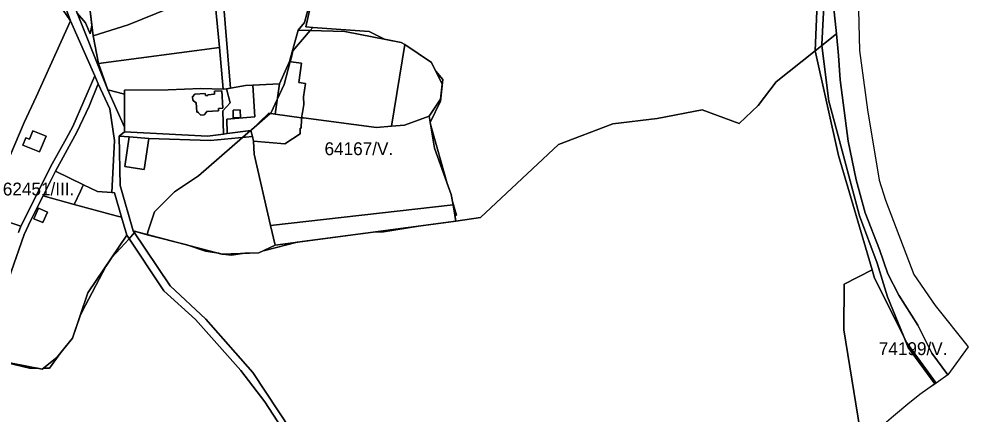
# Model space of a CAD drawing. Extents: x -502026 to -497664, y -1143484 to -1138019.
# Drawn here: x -498590 to -497998, y -1141865 to -1141619 of the extents above; entities that cross this region are included whole.
import ezdxf

# ---------------------------------------------------------------- set-up
doc = ezdxf.new("R2010")
doc.units = 0
for name, color, linetype in [('25', 7, 'Continuous'), ('31', 7, 'Continuous'), ('37', 7, 'Continuous'), ('43', 7, 'Continuous'), ('49', 7, 'Continuous'), ('55', 7, 'Continuous'), ('62', 7, 'Continuous')]:
    doc.layers.add(name, color=color, linetype=linetype)

msp = doc.modelspace()

# ---------------------------------------------------------------- linework, layer by layer
at = {"layer": '25'}
for points in [[(-498462.48, -1141662.97), (-498476.51, -1141662.61), (-498496.86, -1141663.41), (-498524.14, -1141663.5), (-498524.13, -1141666.14), (-498534.51, -1141663.26), (-498540.35, -1141646.84), (-498464.9, -1141637.05)], [(-498334.06, -1141679.76), (-498349.48, -1141685.31), (-498357.49, -1141685.92), (-498349.26, -1141635.03), (-498332.54, -1141646.31), (-498325.9, -1141659.82), (-498327, -1141669.23)], [(-498430.11, -1141678.47), (-498434.11, -1141677.92), (-498445.33, -1141688.68), (-498460.08, -1141690.61), (-498460.31, -1141681.6), (-498442.77, -1141680.09), (-498444.03, -1141660.43), (-498427.35, -1141659.64)], [(-498462.48, -1141662.97), (-498460.46, -1141662.63), (-498458.17, -1141671.36), (-498462.83, -1141676.38), (-498462.4, -1141690.91), (-498472.24, -1141692.2), (-498524.02, -1141689.63), (-498524.04, -1141686.55), (-498524.13, -1141666.14), (-498524.14, -1141663.5), (-498496.86, -1141663.41), (-498476.51, -1141662.61)], [(-498463.44, -1141663.99), (-498467.96, -1141664.27), (-498467.87, -1141666.06), (-498472.1, -1141666.37), (-498472.07, -1141666.85), (-498473.67, -1141666.95), (-498473.74, -1141665.69), (-498480.29, -1141666.13), (-498481.67, -1141667.66), (-498481.52, -1141669.75), (-498479.86, -1141671.22), (-498479.4, -1141671.18), (-498478.93, -1141677.34), (-498478.06, -1141677.28), (-498478.02, -1141677.75), (-498476.5, -1141679.05), (-498474.37, -1141678.93), (-498472.94, -1141677.35), (-498472.96, -1141676.88), (-498465.5, -1141676.39), (-498465.55, -1141674.89), (-498462.76, -1141674.71)], [(-498532.03, -1141727.36), (-498530.29, -1141727.52), (-498525.92, -1141742.8), (-498529.35, -1141741.87), (-498555.48, -1141734.78), (-498551.6, -1141726.45), (-498549.9, -1141722.79), (-498549.76, -1141722.49), (-498540.93, -1141726.8)]]:
    msp.add_lwpolyline(points, close=True, dxfattribs=at)
at = {"layer": '31'}
for points in [[(-498349.26, -1141635.03), (-498357.49, -1141685.92), (-498366.94, -1141686.74), (-498412.32, -1141680.91), (-498413.62, -1141680.73), (-498413.05, -1141677.56), (-498412.15, -1141672.54), (-498412.38, -1141667.61), (-498411.22, -1141659.31), (-498415.3, -1141658.74), (-498413.61, -1141646.71), (-498418.58, -1141646.01), (-498421.21, -1141645.64), (-498415.78, -1141626.22), (-498386.55, -1141627.03), (-498351.49, -1141633.83)], [(-498319.11, -1141735.05), (-498432.94, -1141748.03), (-498443.3, -1141703.42), (-498443.65, -1141695.34), (-498424.08, -1141697), (-498414.58, -1141690.77), (-498414.59, -1141687.27), (-498413.79, -1141687.29), (-498413.64, -1141681.68), (-498413.62, -1141680.73), (-498412.32, -1141680.91), (-498366.94, -1141686.74), (-498357.49, -1141685.92), (-498349.48, -1141685.31), (-498334.06, -1141679.76), (-498330.58, -1141699.76), (-498320.36, -1141728.58)], [(-498521.14, -1141692.7), (-498523.9, -1141711.15), (-498515.99, -1141712.34), (-498511.76, -1141712.97), (-498508.92, -1141693.77), (-498470.48, -1141694.85), (-498444.29, -1141692.51), (-498443.65, -1141695.34), (-498443.3, -1141703.42), (-498432.94, -1141748.03), (-498430.11, -1141760.24), (-498440.19, -1141765.02), (-498463.46, -1141765.75), (-498518.8, -1141751.37), (-498526.77, -1141723.05), (-498527.53, -1141692.29)], [(-498555.48, -1141734.78), (-498529.35, -1141741.87), (-498525.92, -1141742.8), (-498522.72, -1141754.01), (-498546.95, -1141790.01), (-498556.66, -1141818.24), (-498566.28, -1141830.25), (-498575.47, -1141837.59), (-498613.88, -1141829.95), (-498603.5, -1141800.08), (-498596.59, -1141781.61), (-498586.82, -1141753.62), (-498582.48, -1141744.58), (-498574.93, -1141729.51)], [(-498572.26, -1141739.56), (-498577.86, -1141737.22), (-498580.61, -1141743.72), (-498575.01, -1141746.06)]]:
    msp.add_lwpolyline(points, close=True, dxfattribs=at)
at = {"layer": '37'}
for points in [[(-498468.3, -1141600.99), (-498521.83, -1141622.73), (-498543.68, -1141629.6), (-498545.55, -1141614.01), (-498540.19, -1141601.73), (-498472.52, -1141589.85)], [(-498557.86, -1141620.31), (-498579.16, -1141667.75), (-498586.65, -1141683.62), (-498595.46, -1141704.28), (-498611.77, -1141740.81), (-498648.14, -1141728.24), (-498683.59, -1141712.28), (-498669.98, -1141686.66), (-498667.93, -1141675.26), (-498657.61, -1141653.21), (-498650.99, -1141654.52), (-498639.74, -1141648.11), (-498633.36, -1141630.35), (-498644.79, -1141624.98), (-498644.02, -1141617.12), (-498624.09, -1141623.37), (-498616.79, -1141615.76), (-498612.61, -1141616.54), (-498606.51, -1141611.58), (-498603.56, -1141602.08), (-498594.48, -1141602.56), (-498583.73, -1141606.31), (-498572.2, -1141605.96), (-498562.32, -1141613.57)], [(-498468.16, -1141602.47), (-498464.9, -1141637.05), (-498540.35, -1141646.84), (-498543.68, -1141629.6), (-498521.83, -1141622.73), (-498468.3, -1141600.99)], [(-498415.78, -1141626.22), (-498421.21, -1141645.64), (-498427.35, -1141659.64), (-498444.03, -1141660.43), (-498448.55, -1141660.65), (-498458.03, -1141662.23), (-498463.01, -1141601.55), (-498407.52, -1141604.91), (-498411.73, -1141621.35)], [(-498542.66, -1141654.6), (-498556.29, -1141686.3), (-498560.31, -1141693.56), (-498569.25, -1141709.41), (-498588.89, -1141748.42), (-498611.77, -1141740.81), (-498595.46, -1141704.28), (-498586.65, -1141683.62), (-498579.16, -1141667.75), (-498557.86, -1141620.31)], [(-498573.03, -1141692.28), (-498581.23, -1141688.88), (-498583.43, -1141694.19), (-498585.72, -1141693.25), (-498587.59, -1141697.76), (-498577.07, -1141702.1)], [(-498317.26, -1141745.25), (-498430.11, -1141760.24), (-498432.94, -1141748.03), (-498319.11, -1141735.05)], [(-498017.71, -1141846.21), (-498022.83, -1141849.82), (-498027.83, -1141853.34), (-498029.01, -1141854.28), (-498034.07, -1141858.33), (-498044.28, -1141866.85), (-498050.16, -1141871.76), (-498065.32, -1141874.58), (-498075.32, -1141812.96), (-498074.98, -1141784.5), (-498057.54, -1141775.53), (-498056.02, -1141780.8), (-498035.83, -1141821.06)]]:
    msp.add_lwpolyline(points, close=True, dxfattribs=at)
at = {"layer": '43'}
for points in [[(-498090.08, -1141564.22), (-498093.13, -1141638.94), (-498117.43, -1141658.42), (-498128.73, -1141673.11), (-498140.46, -1141684.3), (-498163.59, -1141675.75), (-498191.81, -1141681.3), (-498219.34, -1141684.54), (-498253.35, -1141697.5), (-498301.98, -1141743.03), (-498317.26, -1141745.25), (-498319.11, -1141735.05), (-498320.36, -1141728.58), (-498330.58, -1141699.76), (-498334.06, -1141679.76), (-498327, -1141669.23), (-498325.9, -1141659.82), (-498332.54, -1141646.31), (-498349.26, -1141635.03), (-498351.49, -1141633.83), (-498386.55, -1141627.03), (-498415.78, -1141626.22), (-498411.73, -1141621.35), (-498407.52, -1141604.91)], [(-498562.69, -1141607.49), (-498557.86, -1141620.31), (-498562.32, -1141613.57)], [(-498545.55, -1141614.01), (-498543.68, -1141629.6), (-498540.35, -1141646.84), (-498534.51, -1141663.26), (-498556.46, -1141608.73)], [(-498420.03, -1141875.81), (-498444.04, -1141839.62), (-498473.4, -1141806.35), (-498495.69, -1141785.66), (-498518.8, -1141751.37), (-498463.46, -1141765.75), (-498440.19, -1141765.02), (-498430.11, -1141760.24), (-498317.26, -1141745.25), (-498301.98, -1141743.03), (-498253.35, -1141697.5), (-498219.34, -1141684.54), (-498191.81, -1141681.3), (-498163.59, -1141675.75), (-498140.46, -1141684.3), (-498128.73, -1141673.11), (-498117.43, -1141658.42), (-498093.13, -1141638.94), (-498078.53, -1141704.32), (-498057.54, -1141775.53), (-498074.98, -1141784.5), (-498075.32, -1141812.96), (-498065.32, -1141874.58)], [(-498611.77, -1141740.81), (-498588.89, -1141748.42), (-498590.32, -1141752.32)], [(-498613.88, -1141829.95), (-498575.47, -1141837.59), (-498566.28, -1141830.25), (-498556.66, -1141818.24), (-498546.95, -1141790.01), (-498522.72, -1141754.01), (-498499.6, -1141788.79), (-498479.77, -1141806.48), (-498451.59, -1141838.3), (-498436.54, -1141857.84), (-498423.37, -1141878.17)]]:
    msp.add_lwpolyline(points, dxfattribs=at)
at = {"layer": '49'}
msp.add_lwpolyline([(-498066.45, -1141596.33), (-498065.44, -1141638.73), (-498060.4, -1141675.82), (-498053.14, -1141719.76), (-498049.24, -1141732.06), (-498031.51, -1141778.56), (-498018.34, -1141797.77), (-497997.74, -1141823.63), (-498010.44, -1141841.03), (-498020.42, -1141827.63), (-498029.15, -1141810.09), (-498041.01, -1141791.41), (-498047.77, -1141778.15), (-498052.88, -1141762.94), (-498061.89, -1141740.12), (-498067.62, -1141719.38), (-498072.53, -1141695.32), (-498077.57, -1141657.19), (-498078.46, -1141642.04), (-498079.89, -1141628.43), (-498081.67, -1141610.69)], dxfattribs=at)
at = {"layer": '55'}
for points in [[(-498081.67, -1141610.69), (-498079.89, -1141628.43), (-498093.13, -1141638.94), (-498090.08, -1141564.22)], [(-498423.37, -1141878.17), (-498436.54, -1141857.84), (-498451.59, -1141838.3), (-498479.77, -1141806.48), (-498499.6, -1141788.79), (-498522.72, -1141754.01), (-498525.92, -1141742.8), (-498530.29, -1141727.52), (-498532.03, -1141727.36), (-498530.34, -1141694.84), (-498533.18, -1141675.22), (-498540.46, -1141659.57), (-498542.66, -1141654.6), (-498557.86, -1141620.31), (-498562.69, -1141607.49)], [(-498556.46, -1141608.73), (-498534.51, -1141663.26), (-498524.04, -1141686.55), (-498524.02, -1141689.63), (-498527.53, -1141692.29), (-498526.77, -1141723.05), (-498518.8, -1141751.37), (-498495.69, -1141785.66), (-498473.4, -1141806.35), (-498444.04, -1141839.62), (-498420.03, -1141875.81)], [(-498590.32, -1141752.32), (-498588.89, -1141748.42), (-498569.25, -1141709.41), (-498560.31, -1141693.56), (-498556.29, -1141686.3), (-498542.66, -1141654.6), (-498540.46, -1141659.57), (-498546.22, -1141673.43), (-498553.93, -1141689.66), (-498567.2, -1141714.11), (-498574.93, -1141729.51), (-498582.48, -1141744.58), (-498586.82, -1141753.62), (-498596.59, -1141781.61)]]:
    msp.add_lwpolyline(points, dxfattribs=at)
for points in [[(-498458.03, -1141662.23), (-498460.46, -1141662.63), (-498462.48, -1141662.97), (-498464.9, -1141637.05), (-498468.16, -1141602.47), (-498463.01, -1141601.55)], [(-498010.44, -1141841.03), (-498017.71, -1141846.21), (-498035.83, -1141821.06), (-498056.02, -1141780.8), (-498057.54, -1141775.53), (-498078.53, -1141704.32), (-498093.13, -1141638.94), (-498079.89, -1141628.43), (-498078.46, -1141642.04), (-498077.57, -1141657.19), (-498072.53, -1141695.32), (-498067.62, -1141719.38), (-498061.89, -1141740.12), (-498052.88, -1141762.94), (-498047.77, -1141778.15), (-498041.01, -1141791.41), (-498029.15, -1141810.09), (-498020.42, -1141827.63)], [(-498413.62, -1141680.73), (-498430.11, -1141678.47), (-498427.35, -1141659.64), (-498421.21, -1141645.64), (-498418.58, -1141646.01), (-498413.61, -1141646.71), (-498415.3, -1141658.74), (-498411.22, -1141659.31), (-498412.38, -1141667.61), (-498412.15, -1141672.54), (-498413.05, -1141677.56)], [(-498532.03, -1141727.36), (-498540.93, -1141726.8), (-498549.76, -1141722.49), (-498567.2, -1141714.11), (-498553.93, -1141689.66), (-498546.22, -1141673.43), (-498540.46, -1141659.57), (-498533.18, -1141675.22), (-498530.34, -1141694.84)], [(-498460.08, -1141690.61), (-498462.4, -1141690.91), (-498462.83, -1141676.38), (-498458.17, -1141671.36), (-498460.46, -1141662.63), (-498458.03, -1141662.23), (-498448.55, -1141660.65), (-498444.03, -1141660.43), (-498442.77, -1141680.09), (-498460.31, -1141681.6)], [(-498524.13, -1141666.14), (-498524.04, -1141686.55), (-498534.51, -1141663.26)], [(-498463.44, -1141663.99), (-498462.76, -1141674.71), (-498465.55, -1141674.89), (-498465.5, -1141676.39), (-498472.96, -1141676.88), (-498472.94, -1141677.35), (-498474.37, -1141678.93), (-498476.5, -1141679.05), (-498478.02, -1141677.75), (-498478.06, -1141677.28), (-498478.93, -1141677.34), (-498479.4, -1141671.18), (-498479.86, -1141671.22), (-498481.52, -1141669.75), (-498481.67, -1141667.66), (-498480.29, -1141666.13), (-498473.74, -1141665.69), (-498473.67, -1141666.95), (-498472.07, -1141666.85), (-498472.1, -1141666.37), (-498467.87, -1141666.06), (-498467.96, -1141664.27)], [(-498451.76, -1141680.75), (-498456.22, -1141680.87), (-498456.39, -1141676.06), (-498451.86, -1141675.88)], [(-498451.76, -1141680.75), (-498451.86, -1141675.88), (-498456.39, -1141676.06), (-498456.22, -1141680.87)], [(-498430.11, -1141678.47), (-498413.62, -1141680.73), (-498413.64, -1141681.68), (-498413.79, -1141687.29), (-498414.59, -1141687.27), (-498414.58, -1141690.77), (-498424.08, -1141697), (-498443.65, -1141695.34), (-498444.29, -1141692.51), (-498445.33, -1141688.68), (-498434.11, -1141677.92)], [(-498573.03, -1141692.28), (-498577.07, -1141702.1), (-498587.59, -1141697.76), (-498585.72, -1141693.25), (-498583.43, -1141694.19), (-498581.23, -1141688.88)], [(-498444.29, -1141692.51), (-498470.48, -1141694.85), (-498508.92, -1141693.77), (-498521.14, -1141692.7), (-498527.53, -1141692.29), (-498524.02, -1141689.63), (-498472.24, -1141692.2), (-498462.4, -1141690.91), (-498460.08, -1141690.61), (-498445.33, -1141688.68)], [(-498508.92, -1141693.77), (-498511.76, -1141712.97), (-498515.99, -1141712.34), (-498523.9, -1141711.15), (-498521.14, -1141692.7)], [(-498549.76, -1141722.49), (-498549.9, -1141722.79), (-498551.6, -1141726.45), (-498555.48, -1141734.78), (-498574.93, -1141729.51), (-498567.2, -1141714.11)], [(-498572.26, -1141739.56), (-498575.01, -1141746.06), (-498580.61, -1141743.72), (-498577.86, -1141737.22)]]:
    msp.add_lwpolyline(points, close=True, dxfattribs=at)
at = {"layer": '62'}
for points in [[(-498066.45, -1141596.33), (-498065.44, -1141638.73), (-498060.4, -1141675.82), (-498053.14, -1141719.76), (-498049.24, -1141732.06), (-498031.51, -1141778.56), (-498018.34, -1141797.77), (-497997.74, -1141823.63), (-498010.44, -1141841.03), (-498017.71, -1141846.21), (-498018.52, -1141846.78), (-498035, -1141824), (-498037.99, -1141816.74), (-498038.02, -1141816.67), (-498048, -1141792.5), (-498054.5, -1141771.5), (-498065.5, -1141742), (-498079.5, -1141689), (-498084.5, -1141670.5), (-498088.92, -1141635.6), (-498089, -1141635), (-498087, -1141599)], [(-498087, -1141599), (-498089, -1141635), (-498088.92, -1141635.6), (-498084.5, -1141670.5), (-498079.5, -1141689), (-498065.5, -1141742), (-498054.5, -1141771.5), (-498048, -1141792.5), (-498038.02, -1141816.67), (-498056.02, -1141780.8), (-498057.54, -1141775.53), (-498074.98, -1141784.5), (-498075.32, -1141812.96), (-498065.32, -1141874.58)], [(-498406.5, -1141604.5), (-498411, -1141624), (-498406.5, -1141624.5), (-498408.16, -1141626.43), (-498419, -1141639), (-498420, -1141643), (-498420.72, -1141645.71), (-498424.5, -1141660), (-498428.77, -1141669.35), (-498432.5, -1141677.5), (-498433.14, -1141678.05), (-498444.87, -1141688.24), (-498445.33, -1141688.68), (-498445.39, -1141688.69), (-498450.42, -1141693.06), (-498478, -1141717), (-498493, -1141727), (-498505.5, -1141739.5), (-498509.5, -1141752), (-498509.95, -1141753.67), (-498517.25, -1141751.77), (-498517.99, -1141752.57), (-498521.29, -1141756.16), (-498532.06, -1141767.89), (-498535.82, -1141773.47), (-498550.5, -1141801.5), (-498551.86, -1141804.27), (-498556.66, -1141818.24), (-498563.85, -1141827.22), (-498571, -1141837), (-498574.73, -1141837), (-498575.47, -1141837.59), (-498578.44, -1141837), (-498583.5, -1141837), (-498608.01, -1141831.12)], [(-498608.01, -1141831.12), (-498583.5, -1141837), (-498578.44, -1141837), (-498575.47, -1141837.59), (-498574.73, -1141837), (-498571, -1141837), (-498563.85, -1141827.22), (-498556.66, -1141818.24), (-498551.86, -1141804.27), (-498550.5, -1141801.5), (-498535.82, -1141773.47), (-498532.06, -1141767.89), (-498521.29, -1141756.16), (-498517.99, -1141752.57), (-498517.25, -1141751.77), (-498509.95, -1141753.67), (-498485.19, -1141760.1), (-498473.5, -1141764), (-498465.21, -1141765.29), (-498463.46, -1141765.75), (-498462.49, -1141765.72), (-498457.5, -1141766.5), (-498449.1, -1141765.3), (-498440.19, -1141765.02), (-498437.19, -1141763.6), (-498436.5, -1141763.5), (-498416.41, -1141758.42), (-498368.86, -1141752.1), (-498362.5, -1141752), (-498340.61, -1141748.35), (-498317.26, -1141745.25), (-498317.89, -1141741.79), (-498317, -1141741.5), (-498319.52, -1141732.94), (-498320.36, -1141728.58), (-498322.78, -1141721.77), (-498333.04, -1141685.62), (-498333.37, -1141683.73), (-498327, -1141670.5), (-498325.5, -1141657), (-498329.85, -1141651.77), (-498332.54, -1141646.31), (-498349.26, -1141635.03), (-498351.49, -1141633.83), (-498361.86, -1141631.82), (-498371.5, -1141627), (-498406.5, -1141624.5), (-498411, -1141624), (-498406.5, -1141604.5)], [(-498553.69, -1141615.62), (-498548.5, -1141621.5), (-498545.5, -1141628.5), (-498544.44, -1141623.22), (-498545.55, -1141614.01)], [(-498545.55, -1141614.01), (-498544.44, -1141623.22), (-498545.5, -1141628.5), (-498548.5, -1141621.5), (-498553.69, -1141615.62)]]:
    msp.add_lwpolyline(points, dxfattribs=at)
for points in [[(-498509.95, -1141753.67), (-498509.5, -1141752), (-498505.5, -1141739.5), (-498493, -1141727), (-498478, -1141717), (-498450.42, -1141693.06), (-498445.39, -1141688.69), (-498445.33, -1141688.68), (-498444.87, -1141688.24), (-498433.14, -1141678.05), (-498432.5, -1141677.5), (-498428.77, -1141669.35), (-498424.5, -1141660), (-498420.72, -1141645.71), (-498420, -1141643), (-498419, -1141639), (-498408.16, -1141626.43), (-498406.5, -1141624.5), (-498371.5, -1141627), (-498361.86, -1141631.82), (-498351.49, -1141633.83), (-498349.26, -1141635.03), (-498332.54, -1141646.31), (-498329.85, -1141651.77), (-498325.5, -1141657), (-498327, -1141670.5), (-498333.37, -1141683.73), (-498333.04, -1141685.62), (-498322.78, -1141721.77), (-498320.36, -1141728.58), (-498319.52, -1141732.94), (-498317, -1141741.5), (-498317.89, -1141741.79), (-498317.26, -1141745.25), (-498340.61, -1141748.35), (-498362.5, -1141752), (-498368.86, -1141752.1), (-498416.41, -1141758.42), (-498436.5, -1141763.5), (-498437.19, -1141763.6), (-498440.19, -1141765.02), (-498449.1, -1141765.3), (-498457.5, -1141766.5), (-498462.49, -1141765.72), (-498463.46, -1141765.75), (-498465.21, -1141765.29), (-498473.5, -1141764), (-498485.19, -1141760.1)], [(-498038.02, -1141816.67), (-498037.99, -1141816.74), (-498035, -1141824), (-498018.52, -1141846.78), (-498022.83, -1141849.82), (-498027.83, -1141853.34), (-498029.01, -1141854.28), (-498034.07, -1141858.33), (-498044.28, -1141866.85), (-498050.16, -1141871.76), (-498065.32, -1141874.58), (-498075.32, -1141812.96), (-498074.98, -1141784.5), (-498057.54, -1141775.53), (-498056.02, -1141780.8)]]:
    msp.add_lwpolyline(points, close=True, dxfattribs=at)

# ---------------------------------------------------------------- texts
for s, p in [('64167/V.', (-498399.28, -1141704.07)), ('62451/III.', (-498600.05, -1141729.21)), ('74199/V.', (-498053.4, -1141828.75))]:
    msp.add_text(s, height=8, dxfattribs=at).set_placement(p)

doc.saveas('drawing.dxf')
